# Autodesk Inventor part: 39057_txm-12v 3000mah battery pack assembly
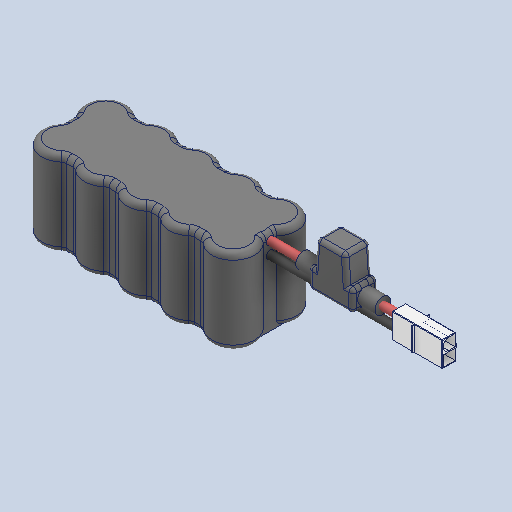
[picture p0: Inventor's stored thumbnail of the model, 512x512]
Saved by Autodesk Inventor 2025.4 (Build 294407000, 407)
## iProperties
Created: 2017-01
Part Number: 39057_txm-12v 3000mah battery pack assembly
Material: Genérico
Description: STEP AP214
Document SubType Name: Modeling
Designer: usuario
Density: 1 g/cm^3
Appearance: Valor por defecto
Title: 39057 TETRIX 12V 3000mAH Battery Pack Assembly.STEP
Revision Number: ANY
Sending System: SolidWorks 2016
Preprocessor: SwSTEP 2.0
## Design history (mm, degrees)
feature "39057 TETRIX 12V 3000mAH Battery Pack-1-solid1"
feature "Battery Pack Fuse Holder-1-solid1"
feature "Tamiya Battery Plug-1-solid1"
node "Sólido1"
node "Sólido2"
node "Sólido3"
